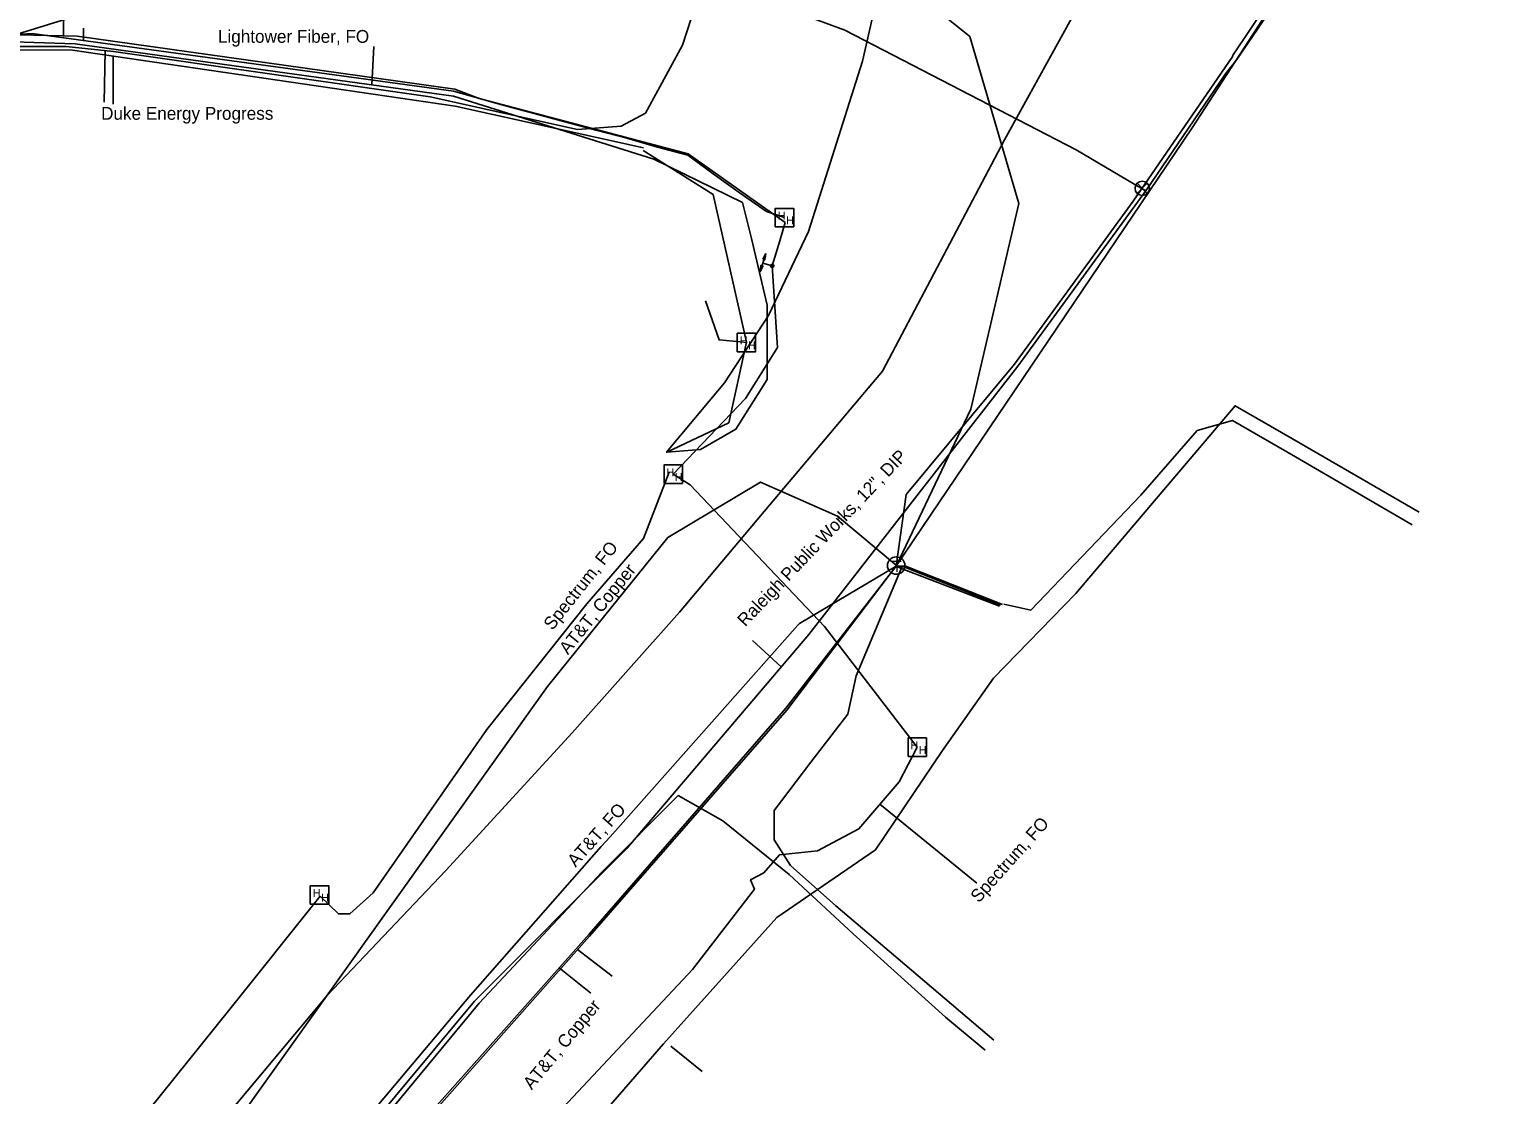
# Model space of a CAD drawing. Extents: x 2070721 to 2083340, y 729290 to 737883.
# Drawn here: x 2081646.1 to 2082100.6, y 734630.1 to 734963.1 of the extents above; entities that cross this region are included whole.
import ezdxf

# ---------------------------------------------------------------- set-up
doc = ezdxf.new("R2010")
doc.units = 0
for name, color, linetype in [('Exist Utilities Other Unknown UG SUE LOS B', 7, 'Continuous'), ('Exist Utilities Power Hand Hole CELL', 7, 'Continuous'), ('Exist Utilities Power UG Cable SUE LOS B', 7, 'Continuous'), ('Exist Utilities Power UG Cable SUE LOS B Leader', 7, 'Continuous'), ('Exist Utilities Power UG Cable SUE LOS B Text', 7, 'Continuous'), ('Exist Utilities Power UG Cable SUE LOS C', 7, 'Continuous'), ('Exist Utilities Telephone Manhole CELL', 7, 'Continuous'), ('Exist Utilities Telephone UG Cable SUE LOS C', 7, 'Continuous'), ('Exist Utilities Telephone UG Cable SUE LOS C Leader', 7, 'Continuous'), ('Exist Utilities Telephone UG Cable SUE LOS C Text', 7, 'Continuous'), ('Exist Utilities Telephone UG Conduit SUE LOS B', 7, 'Continuous'), ('Exist Utilities Telephone UG FO SUE LOS B', 7, 'Continuous'), ('Exist Utilities Telephone UG FO SUE LOS B Leader', 7, 'Continuous'), ('Exist Utilities Telephone UG FO SUE LOS B Text', 7, 'Continuous'), ('Exist Utilities Telephone UG FO SUE LOS C', 7, 'Continuous'), ('Exist Utilities TV Change of Service SUE CELL', 7, 'Continuous'), ('Exist Utilities TV Hand Hole CELL', 7, 'Continuous'), ('Exist Utilities TV UG Cable SUE LOS B', 7, 'Continuous'), ('Exist Utilities TV UG Cable SUE LOS B Leader', 7, 'Continuous'), ('Exist Utilities TV UG FO Cable SUE LOS B', 7, 'Continuous'), ('Exist Utilities TV UG FO Cable SUE LOS B Leader', 7, 'Continuous'), ('Exist Utilities TV UG FO Cable SUE LOS B Text', 7, 'Continuous'), ('Exist Utilities TV UG FO Cable SUE LOS C', 7, 'Continuous'), ('Exist Utilities Water UG Line SUE LOS B', 7, 'Continuous'), ('Exist Utilities Water UG Line SUE LOS B Leader', 7, 'Continuous'), ('Exist Utilities Water UG Line SUE LOS B Text', 7, 'Continuous'), ('Exist Utilities Water Valve CELL', 7, 'Continuous')]:
    doc.layers.add(name, color=color, linetype=linetype)

msp = doc.modelspace()

# ---------------------------------------------------------------- linework, layer by layer
at = {"layer": 'Exist Utilities Other Unknown UG SUE LOS B'}
msp.add_lwpolyline([(2081599.02, 734480.52), (2081638.91, 734537.92), (2081689.31, 734601.45), (2081739.23, 734661.21), (2081776.34, 734700.28), (2081815.77, 734743.2), (2081849.28, 734780.93), (2081877.42, 734814.37), (2081912.75, 734856.19), (2081950.81, 734928.53), (2081978.43, 734978.59)], dxfattribs=at)
at = {"layer": 'Exist Utilities Power Hand Hole CELL'}
msp.add_line((2081870.31, 734865.04), (2081870.31, 734865.04), dxfattribs=at)
msp.add_lwpolyline([(2081867.36, 734862.32), (2081873.11, 734862.32), (2081873.11, 734868.07), (2081867.36, 734868.07), (2081867.36, 734862.32)], dxfattribs=at)
at = {"layer": 'Exist Utilities Power UG Cable SUE LOS B'}
for p, q in [((2082040.83, 734835.09), (2082080.39, 734812.16)), ((2082041.73, 734829.45), (2082078.24, 734808.22))]:
    msp.add_line(p, q, dxfattribs=at)
for points in [[(2081128.97, 734740.08), (2081231.48, 734798.66), (2081295.17, 734834.12), (2081365.43, 734871.31), (2081433.71, 734899.92), (2081452.63, 734907.74), (2081490.45, 734923.08), (2081565.19, 734950.13), (2081621.73, 734956.73), (2081659.71, 734956.5), (2081779.27, 734939), (2081838.04, 734926)], [(2081845.21, 734830.86), (2081864.69, 734840.12), (2081870.23, 734865.29), (2081859.8, 734911.4), (2081837.99, 734925.16)], [(2081857.43, 734878.23), (2081861.69, 734866.04), (2081870.52, 734865.2)], [(2081747.02, 734534.16), (2081777.19, 734567.94), (2081814.78, 734612), (2081844.33, 734646.12), (2081879.78, 734685.51), (2081910.59, 734706.71), (2081931.49, 734737.7), (2081947.42, 734760.31), (2081973.14, 734786.73), (2081997.07, 734814.98), (2082022.89, 734845.44), (2082040.83, 734835.09)], [(2081950.65, 734783.48), (2081959.1, 734781.59), (2081993.49, 734817.45), (2082011.05, 734837.68), (2082022.07, 734840.85), (2082041.73, 734829.45)]]:
    msp.add_lwpolyline(points, dxfattribs=at)
at = {"layer": 'Exist Utilities Power UG Cable SUE LOS B Leader'}
for p, q in [((2081669.9, 734956.32), (2081669.61, 734940.23)), ((2081672.4, 734954.58), (2081672.4, 734939.68)), ((2081846.67, 734645.35), (2081856.43, 734637.48))]:
    msp.add_line(p, q, dxfattribs=at)
at = {"layer": 'Exist Utilities Power UG Cable SUE LOS C'}
for points in [[(2080186.05, 734475.29), (2080187.03, 734475.63), (2080448.94, 734565.1), (2080663.08, 734641.37), (2080827.26, 734699.95), (2080984.4, 734756.05), (2081109.44, 734801.16), (2081210.88, 734831.9), (2081586.98, 734944.46), (2081830.55, 735019.69), (2082038.54, 735143.44), (2082248.34, 735270.09)], [(2081398.46, 734886.3), (2081460.49, 734911.77), (2081509.14, 734930.55), (2081563.83, 734950.54), (2081592.79, 734954.64), (2081621.06, 734958.42), (2081630.74, 734957.65), (2081639.48, 734957.65), (2081657.7, 734957.65), (2081672.52, 734956.07), (2081771.45, 734941.91), (2081817.43, 734931.74), (2081831.08, 734932.73), (2081838.68, 734936.87), (2081850.29, 734958.08), (2081862.4, 734995.7), (2081864.93, 735002.95)]]:
    msp.add_lwpolyline(points, dxfattribs=at)
at = {"layer": 'Exist Utilities Telephone Manhole CELL'}
msp.add_circle((2081917.02, 734795.5), 2.72, dxfattribs=at)
at = {"layer": 'Exist Utilities Telephone UG Cable SUE LOS C'}
msp.add_line((2081889.65, 734899.84), (2081906.46, 734953.04), dxfattribs=at)
for points in [[(2080527.18, 734594.58), (2080756.63, 734677.7), (2080975.53, 734755.33), (2081114.85, 734806.49), (2081251.31, 734880.3), (2081357.91, 734934.96), (2081407.46, 734955.63), (2081557.34, 735013.56), (2081611.19, 735031.21), (2081670.8, 735036.79), (2081727.82, 735033.26), (2081796.62, 735020.83), (2081876.61, 734998.57), (2081913.61, 734982.12), (2081940.08, 734960.79), (2081955.36, 734908.6), (2081940.34, 734844.38), (2081917.15, 734795.51)], [(2080934.26, 734720.97), (2081041, 734761.39), (2081061.56, 734773.15), (2081150.65, 734813.71), (2081201.33, 734846.96), (2081300.64, 734903.05), (2081400.2, 734948.86), (2081476.71, 734979.23), (2081590.79, 735021.91), (2081620.53, 735029.68), (2081685.91, 735033.08), (2081745.92, 735027.46), (2081824.22, 735009.88), (2081875.43, 734995.15), (2081909.49, 734979.28), (2081909.49, 734966.35), (2081906.46, 734953.04)], [(2081845.25, 734830.92), (2081863.4, 734852.6), (2081877.12, 734873.61), (2081889.65, 734899.84)], [(2080953.21, 732796.69), (2081054.09, 733077.62), (2081111.09, 733245.57), (2081176.08, 733423.78), (2081231.97, 733580.28), (2081320.16, 733847.08), (2081418.84, 734093.09), (2081467.34, 734224.03), (2081494.06, 734287.2), (2081526.74, 734352.01), (2081556, 734404.62), (2081808.13, 734757.73), (2081845.73, 734804.26), (2081874.67, 734821.58), (2081898.66, 734810.94), (2081917.15, 734795.51)], [(2081675.15, 734515.17), (2081731.28, 734579.5), (2081761.87, 734613.73), (2081821.11, 734680.35), (2081882.55, 734750.91), (2081917.05, 734795.26)], [(2081675.44, 734514.41), (2081731.46, 734578.64), (2081762.11, 734613), (2081821.17, 734679.68), (2081882.84, 734750.34), (2081917.15, 734795.51)], [(2081890.41, 734734.05), (2081901.92, 734749.12), (2081904.55, 734761.09), (2081918.76, 734794.96)], [(2081890.41, 734734.05), (2081878.89, 734718.98), (2081878.89, 734709.84), (2081884.04, 734701.82), (2081898.12, 734689.22), (2081947.49, 734647.24)], [(2081671.19, 734518.01), (2081739, 734601.03), (2081786.76, 734658.83), (2081825.08, 734699.74), (2081848.94, 734723.65), (2081862.89, 734715.73), (2081883.59, 734698.93), (2081903.62, 734680.48), (2081932.44, 734654.41), (2081944.85, 734644.1)]]:
    msp.add_lwpolyline(points, dxfattribs=at)
at = {"layer": 'Exist Utilities Telephone UG Cable SUE LOS C Leader'}
for p, q in [((2081817.5, 734675.55), (2081828.33, 734667.26)), ((2081811.7, 734669.77), (2081821.62, 734661.91))]:
    msp.add_line(p, q, dxfattribs=at)
at = {"layer": 'Exist Utilities Telephone UG Conduit SUE LOS B'}
for points in [[(2081917.15, 734795.51), (2082009.52, 734932.29), (2082048.72, 734992.73), (2082076.42, 735035.03), (2082121.27, 735105.83), (2082143.4, 735134.38), (2082165.12, 735153.55), (2082206.17, 735181.11), (2082253.91, 735195.11), (2082261.15, 735199.69), (2082263.21, 735230.16), (2082267.94, 735269.33), (2082270.97, 735300.6), (2082279.44, 735366.27), (2082282.16, 735384.08), (2082312.89, 735448.88), (2082332.37, 735470.01), (2082345.07, 735482.69), (2082399.03, 735538.34), (2082399, 735549.46), (2082395.14, 735556.12)], [(2082022.07, 734954.73), (2082065.19, 735019.13), (2082087.45, 735054.31), (2082120.86, 735106.65)], [(2081917.05, 734795.26), (2081920.12, 734817.65), (2081953.94, 734858.43), (2081991.01, 734909.31), (2082022.17, 734954.69)], [(2081917.05, 734795.26), (2081919.73, 734795.41), (2081950.23, 734783.31)], [(2081917.05, 734795.26), (2081918.94, 734794.52), (2081949.33, 734782.83)], [(2081949.65, 734783.15), (2081919.4, 734795.09), (2081917.05, 734795.26)]]:
    msp.add_lwpolyline(points, dxfattribs=at)
at = {"layer": 'Exist Utilities Telephone UG FO SUE LOS B'}
for points in [[(2081099.85, 734724.62), (2081112.42, 734732.94), (2081128.56, 734742.73), (2081231.52, 734800.87), (2081294.72, 734835.92), (2081365.04, 734873.38), (2081431.01, 734900.6), (2081452.87, 734909.38), (2081490.35, 734924.36), (2081564.77, 734951.57), (2081615.8, 734959.97), (2081660.54, 734958.55), (2081778.72, 734942.12), (2081841.31, 734922.44), (2081868.96, 734908.94)], [(2081827.69, 734710.71), (2081886.29, 734776.88), (2081886.77, 734777.45), (2081917.05, 734795.26)], [(2081542.88, 734322.62), (2081574.46, 734383.49), (2081629.3, 734469.05), (2081685.73, 734544.41), (2081784.03, 734661.28), (2081824.87, 734707.78), (2081827.69, 734710.71)]]:
    msp.add_lwpolyline(points, dxfattribs=at)
at = {"layer": 'Exist Utilities Telephone UG FO SUE LOS B Leader'}
msp.add_line((2081753.18, 734945.73), (2081753.87, 734957.67), dxfattribs=at)
at = {"layer": 'Exist Utilities Telephone UG FO SUE LOS C'}
msp.add_lwpolyline([(2081845.48, 734830.94), (2081855.86, 734831.71), (2081866.94, 734838.07), (2081876.73, 734853.65), (2081876.73, 734876.9), (2081871.84, 734897.65), (2081868.96, 734908.94)], dxfattribs=at)
at = {"layer": 'Exist Utilities TV Change of Service SUE CELL'}
for p, q in [((2081876.25, 734893), (2081874.53, 734887.29)), ((2081875.34, 734890), (2081876.25, 734893)), ((2081878.3, 734889.11), (2081875.34, 734890)), ((2081878.3, 734889.11), (2081878.3, 734889.11))]:
    msp.add_line(p, q, dxfattribs=at)
for points in [[(2081876.25, 734893), (2081876.01, 734891.02), (2081875.8, 734891.52), (2081875.4, 734891.24)], [(2081874.53, 734887.29), (2081874.77, 734889.28), (2081874.98, 734888.78), (2081875.38, 734889.06)]]:
    msp.add_lwpolyline(points, close=True, dxfattribs=at)
msp.add_circle((2081878.3, 734889.11), 0.517, dxfattribs=at)
at = {"layer": 'Exist Utilities TV Hand Hole CELL'}
for p, q in [((2081882.13, 734904.21), (2081882.13, 734904.21)), ((2081847.37, 734824.04), (2081847.37, 734824.04)), ((2081923.61, 734738.76), (2081923.61, 734738.76)), ((2081736.86, 734692.57), (2081736.86, 734692.57))]:
    msp.add_line(p, q, dxfattribs=at)
for points in [[(2081879.26, 734901.33), (2081885.01, 734901.33), (2081885.01, 734907.08), (2081879.26, 734907.08), (2081879.26, 734901.33)], [(2081844.5, 734821.17), (2081850.25, 734821.17), (2081850.25, 734826.92), (2081844.5, 734826.92), (2081844.5, 734821.17)], [(2081920.73, 734735.88), (2081926.48, 734735.88), (2081926.48, 734741.63), (2081920.73, 734741.63), (2081920.73, 734735.88)], [(2081733.99, 734689.7), (2081739.74, 734689.7), (2081739.74, 734695.45), (2081733.99, 734695.45), (2081733.99, 734689.7)]]:
    msp.add_lwpolyline(points, dxfattribs=at)
at = {"layer": 'Exist Utilities TV UG Cable SUE LOS B'}
for points in [[(2081437.24, 734904.54), (2081521.81, 734938.42), (2081585.32, 734957.8), (2081647.07, 734961.7), (2081778.73, 734943.71)], [(2081778.73, 734943.71), (2081783.92, 734942.29), (2081793.79, 734939.4), (2081803.89, 734936.7), (2081813.54, 734934.08), (2081823.2, 734931.54), (2081832.91, 734929.03), (2081842.5, 734926.17), (2081851.98, 734923.76), (2081859.87, 734917.84), (2081867.93, 734912.05), (2081876.48, 734906.11), (2081882.13, 734904.21)]]:
    msp.add_lwpolyline(points, dxfattribs=at)
at = {"layer": 'Exist Utilities TV UG Cable SUE LOS B Leader'}
msp.add_line((2081663.14, 734959.52), (2081663.14, 734963.39), dxfattribs=at)
at = {"layer": 'Exist Utilities TV UG FO Cable SUE LOS B'}
for points in [[(2081119.77, 734739.04), (2081129.02, 734745.24), (2081193.81, 734780.91), (2081230.47, 734802.17), (2081292.91, 734838.4), (2081363.18, 734875.86), (2081429.44, 734902.7), (2081451.9, 734911.7), (2081489.36, 734926.43), (2081564.05, 734954.16), (2081615.43, 734961.96), (2081661.12, 734960.94), (2081779.14, 734944.37)], [(2081779.14, 734944.37), (2081786.75, 734941.47), (2081852.08, 734924.1), (2081882.39, 734902.72)], [(2081878.3, 734889.11), (2081880.65, 734896.93), (2081882.39, 734902.72)], [(2081737.07, 734692.25), (2081742.78, 734686.66), (2081746.35, 734686.66), (2081753.66, 734693.25), (2081789.12, 734744.3), (2081820.35, 734783.54), (2081838.12, 734804), (2081846.1, 734824.65)], [(2081847.37, 734824.04), (2081852.66, 734820.72), (2081894.64, 734776.42), (2081923.55, 734738.76)], [(2081778.59, 734589.45), (2081774.62, 734600.43), (2081794.64, 734621.57), (2081803.63, 734616.23), (2081853.41, 734669.28), (2081872.71, 734694.38), (2081871.55, 734697.36), (2081875.65, 734699.45), (2081880.56, 734705.11), (2081892.44, 734706.39), (2081905.37, 734713.26), (2081917.92, 734727.97), (2081923.61, 734738.76)], [(2081622.95, 734557.31), (2081645.25, 734577.74), (2081708.9, 734656.89), (2081737.07, 734692.25)]]:
    msp.add_lwpolyline(points, dxfattribs=at)
at = {"layer": 'Exist Utilities TV UG FO Cable SUE LOS B Leader'}
for p, q in [((2081656.86, 734960.96), (2081656.86, 734969.6)), ((2081911.96, 734720.96), (2081942.19, 734696.32))]:
    msp.add_line(p, q, dxfattribs=at)
at = {"layer": 'Exist Utilities TV UG FO Cable SUE LOS C'}
msp.add_lwpolyline([(2081878.3, 734889.11), (2081879.9, 734863.62), (2081870, 734847.65), (2081847.37, 734824.04)], dxfattribs=at)
at = {"layer": 'Exist Utilities Water UG Line SUE LOS B'}
msp.add_line((2082066.86, 735017.58), (2082023.39, 734953.58), dxfattribs=at)
for points in [[(2080902.52, 734692.58), (2081024.44, 734735.33), (2081064.65, 734749.07), (2081167.38, 734801.25), (2081288.56, 734870.47), (2081329.8, 734893.5), (2081435.94, 734938.99), (2081596, 735000.71), (2081611.53, 735004.3), (2081650.19, 735007.99), (2081750.43, 735003.6), (2081775.33, 734999.48), (2081852.16, 734980.94), (2081900.97, 734962.81), (2081973.29, 734925.34), (2081993.87, 734913.23), (2081994.94, 734912.69)], [(2081832.89, 734707.14), (2081836.89, 734711.88), (2081889.78, 734773.96), (2081955.02, 734857.75), (2081995.25, 734912.92), (2082019.91, 734949.11), (2082023.39, 734953.58)], [(2081545.19, 734320.14), (2081577.78, 734381.02), (2081631.24, 734467.17), (2081690.06, 734544.38), (2081695.68, 734551.66), (2081723.83, 734585.62), (2081785.29, 734659.45), (2081832.89, 734707.14)]]:
    msp.add_lwpolyline(points, dxfattribs=at)
at = {"layer": 'Exist Utilities Water UG Line SUE LOS B Leader'}
msp.add_line((2081881.14, 734763.9), (2081872.17, 734772.1), dxfattribs=at)
at = {"layer": 'Exist Utilities Water Valve CELL'}
msp.add_lwpolyline([(2081995.47, 734914.93), (2081992.31, 734911.78), (2081993.89, 734913.35), (2081995.47, 734911.78), (2081992.31, 734914.93)], dxfattribs=at)
msp.add_circle((2081993.89, 734913.35), 2.23, dxfattribs=at)

# ---------------------------------------------------------------- texts
at = {"layer": 'Exist Utilities Power Hand Hole CELL'}
for p in [(2081868.15, 734864.57), (2081870.72, 734863.05)]:
    msp.add_text('H', height=2.5, dxfattribs=at).set_placement(p)
at = {"layer": 'Exist Utilities Power UG Cable SUE LOS B Text'}
msp.add_text('Duke Energy Progress', height=4, dxfattribs=at).set_placement((2081668.64, 734934.78))
at = {"layer": 'Exist Utilities Telephone Manhole CELL'}
msp.add_text('T', height=3.5, dxfattribs=at).set_placement((2081915.85, 734793.49))
at = {"layer": 'Exist Utilities Telephone UG Cable SUE LOS C Text'}
for rotation, p in [(51.0614, (2081814.47, 734767.46)), (50.4232, (2081803.18, 734631.49))]:
    msp.add_text('AT&T, Copper', height=4, rotation=rotation, dxfattribs=at).set_placement(p)
at = {"layer": 'Exist Utilities Telephone UG FO SUE LOS B Text'}
msp.add_text('Lightower Fiber, FO ', height=4, dxfattribs=at).set_placement((2081705.13, 734958.82))
msp.add_text('AT&T, FO', height=4, rotation=48.4713, dxfattribs=at).set_placement((2081816.88, 734701.07))
at = {"layer": 'Exist Utilities TV Hand Hole CELL'}
for p in [(2081880.04, 734903.56), (2081882.62, 734902.1), (2081845.28, 734823.4), (2081847.86, 734821.94), (2081921.52, 734738.11), (2081924.1, 734736.65), (2081734.77, 734691.92), (2081737.35, 734690.46)]:
    msp.add_text('H', height=2.5, dxfattribs=at).set_placement(p)
at = {"layer": 'Exist Utilities TV UG FO Cable SUE LOS B Text'}
for s, rotation, p in [('Spectrum, FO', 51.4876, (2081809.64, 734775.04)), ('Spectrum, FO ', 48.1792, (2081942.83, 734689.91))]:
    msp.add_text(s, height=4, rotation=rotation, dxfattribs=at).set_placement(p)
at = {"layer": 'Exist Utilities Water UG Line SUE LOS B Text'}
msp.add_text('Raleigh Public Works, 12", DIP ', height=4, rotation=46.3075, dxfattribs=at).set_placement((2081869.87, 734776.18))

doc.saveas('drawing.dxf')
